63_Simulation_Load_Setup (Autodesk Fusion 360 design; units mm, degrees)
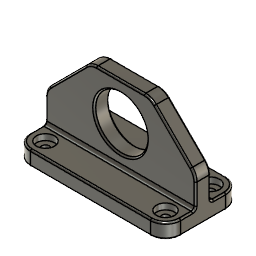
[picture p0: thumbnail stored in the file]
part number: 2026-07-20-13-25-26-316
sketch "Sketch1" plane through (0, 0, 0) normal (0, 1, 0) x axis (1, 0, 0)
  line L1 (-50, 25) -> (50, 25)
  line L2 (-50, -25) -> (-50, 25)
  line L3 (50, -25) -> (-50, -25)
  line L4 (50, 25) -> (50, -25)
  line L5 (-50, -25) -> (50, 25)
  line L6 (50, -25) -> (-50, 25)
  point P6 (0, 0)
  point P1 (0, 0)
  point P4 (-50, -25)
  point P5 (50, -25)
  point P3 (-50, 25)
  horizontal L1
  perpendicular L1 L2
  parallel L1 L3
  parallel L2 L4
  coincident L5 P6
  coincident L6 P6
  coincident P1 P6
  dimension "d2" distance P4 P5 = 100
  dimension "d3" distance P3 P4 = 50
extrude "Extrude1" new body sketch "Sketch1" profile of L1 L2 L3 L4 distance 10
sketch "Sketch2" plane through (0, 0, -25) normal (0, 0, -1) x axis (1, 0, 0)
  line L1 (-50, -5) -> (-50, 5)
  line L2 (50, -5) -> (-50, -5)
  line L3 (50, 5) -> (50, -5)
  line L4 (-50, 5) -> (50, 5)
  line L5 (-50, -25) -> (50, -25)
  line L6 (-50, 25) -> (-50, -25)
  line L7 (50, 25) -> (-50, 25)
  line L8 (50, -25) -> (50, 25)
  line L9 (-50, 25) -> (50, -25)
  line L10 (50, 25) -> (-50, -25)
  point P10 (0, 0)
  point P1 (0, 0)
  point P5 (50, 5)
  point P7 (-50, -25)
  point P8 (-50, 25)
  horizontal L5
  perpendicular L5 L6
  parallel L5 L7
  parallel L6 L8
  coincident L9 P10
  coincident L10 P10
  coincident P1 P10
  coincident P5 L8
  dimension "d6" distance P7 P8 = 50
extrude "Extrude2" add sketch "Sketch2" profile of L1 L2 L3 L4 L5 L6 L7 L8 along normal blind 10
chamfer "Chamfer1" sketch "Sketch2" distance 30
sketch "Sketch3" plane through (0, -5, 0) normal (0, -1, 0) x axis (1, 0, 0)
  line L1 (20, 25) -> (50, -5)
  line L2 (-20, 25) -> (20, 25)
  line L3 (-50, -5) -> (-20, 25)
  line L4 (-50, -25) -> (-50, -5)
  line L5 (50, -25) -> (-50, -25)
  line L6 (50, -5) -> (50, -25)
  circle C1 centre (0, 0) radius 17.5
  point P1 (0, 0)
  point P8 (0, 0)
  coincident P1 P8
  dimension "d10" diameter C1 = 35
extrude "Extrude3" cut sketch "Sketch3" profile of C1 no distance stored
fillet "Fillet1" radius 10
fillet "Fillet2" radius 10
sketch "Sketch4" plane through (0, 0, -25) normal (0, 0, 1) x axis (-1, 0, 0)
  line L1 (50, -5) -> (50, -15)
  line L2 (-50, -5) -> (50, -5)
  line L3 (-50, -15) -> (-50, -5)
  line L4 (40, -25) -> (-40, -25)
  line L5 (-40, 25) -> (40, 25)
  line L6 (-50, 5) -> (-50, 15)
  line L7 (50, 5) -> (-50, 5)
  line L8 (50, 15) -> (50, 5)
  arc A1 centre (40, -15) radius 10 clockwise from (50, -15) to (40, -25)
  arc A2 centre (-40, -15) radius 10 clockwise from (-40, -25) to (-50, -15)
  arc A3 centre (40, 15) radius 10 clockwise from (40, 25) to (50, 15)
  arc A4 centre (-40, 15) radius 10 clockwise from (-50, 15) to (-40, 25)
  point P9 (-40, -15)
  point P18 (-40, -15)
  point P4 (40, -15)
  point P19 (40, -15)
  point P12 (40, 15)
  point P20 (40, 15)
  point P15 (-40, 15)
  point P21 (-40, 15)
  coincident P9 P18
  coincident P4 P19
  coincident P12 P20
  coincident P15 P21
hole "Hole1" sketch "Sketch2" HoleDiameter 5 TipAngle 118 CBDepth 4 CBDiameter 12
fillet "Fillet3" radius 2
fillet "Fillet4" radius 1
chamfer "Chamfer2" sketch "Sketch2" distance 1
